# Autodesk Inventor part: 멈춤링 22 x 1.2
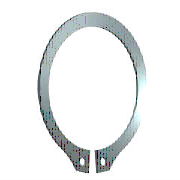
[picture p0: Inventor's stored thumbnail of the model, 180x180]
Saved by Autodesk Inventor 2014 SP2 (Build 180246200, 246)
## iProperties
IsCustomPart: 0
Created: 2015-11
Part Number: 멈춤링 22 x 1.2
Material: 스테인리스강
Description: 리테이닝 링(C형)
Document SubType Name: Modeling
Standard: KS B 1336
Designer: mdu
Standards Organization: KS
Language: ko-KR
Size Designation: 22 x 1.2
Categories: <MemberInstance><Categories><Category DisplayName="샤프트 부품" InternalName="7f7aeb1f-a693-4053-b835-cee3144e0d98" Mnemonic="SHFT"><Category DisplayName="써클립" Inter
Density: 8.08 g/cm^3
Appearance: 반광택
Mass: 1.87978 g
Surface Area: 5.91219 cm^2
Volume: 0.232646 cm^3
Author: mdu
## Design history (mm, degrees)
sketch "스케치1"
  geometry: L1 (-6, 0)-(6, 0) reference; L2 (0, 20.189)-(0, -80.536) reference; L3 (-48.09, 0)-(48.09, 0) reference; L4 (-0.5, -21.488)-(-0.5, -25.588); L5 (-0.5, -6.54)-(-0.5, -13.29); L6 (-2.795, 2.7)-(3.672, 2.7); L7 (0.5, -6.54)-(0.5, -13.29); L8 (0.5, -21.488)-(0.5, -25.588); C1 r 1 at (-2, -23.437); C2 r 1 at (2, -23.437); A1 r 10.5 centre (0, -11) between (0.5, -21.488) and (-0.5, -21.488); A2 r 13.025 centre (0, -10.325) between (5.149, -22.289) and (-5.149, -22.289); A3 r 14.597 centre (0, -11) between (-2.318, -25.411) and (-0.5, -25.588); A4 r 2 centre (-2, -23.437) between (-3.97, -23.781) and (-2.318, -25.411); A5 r 2 centre (-5.94, -24.126) between (-3.97, -23.781) and (-5.149, -22.289); A6 r 2 centre (5.94, -24.126) between (5.149, -22.289) and (3.97, -23.781); A7 r 2 centre (2, -23.437) between (2.318, -25.411) and (3.97, -23.781); A8 r 14.597 centre (0, -11) between (0.5, -25.588) and (2.318, -25.411)
  constraints: 16 point on circle, 12 end point, 10 centre point, 9 symmetric about line, 5 point on line, 4 tangent, 3 coincident, 2 horizontal, 1 perpendicular, 1 vertical, 5 other
  dimensions: "d0" = 21 diameter of A1 (= ND); "d1" = 4.1 distance of L4.end L4.start (= SRB2); "d6" = 0.5 distance between parallel lines of L2 L5 (= 0.25 x SD5); "d7" = 2.7 distance between parallel lines of L6 L3 (= SRB1); "d8" = 0.675 distance of A1.centre A2.centre (= 0.25 x SRB1); "d9" = 2 radius of A4 (= SD5); "d10" = 2 radius of A5 (= SD5); "d11" = 1.5 distance from line of L4 A4.centre (= 0.75 x SD5); "d12" = 2 diameter of C1 (= SD5); "d13" = 2 diameter of C2 (= SD5); "d14" = 11 distance from line of A1.centre L1 (= 0.5 x WD)
extrude "본체" new body sketch "스케치1" distance "d2" = 1.2 (= SD); taper "d3" = 0 deg
workaxis "Work Axis1"
workplane "Work Plane1"
body "Solid1"
other parameters: "WD" = 22 (= WDMIN) [user parameter; used in 1 equation term], "SD" = 1.2 [user parameter; used in 1 equation term], "SRB1" = 2.7 [user parameter; used in 2 equation terms], "ND" = 21 [user parameter; used in 1 equation term], "SRB2" = 4.1 [user parameter; used in 1 equation term], "SD5" = 2 [user parameter; used in 6 equation terms], "d15" = 0, "d16" = 0, "d17" = 0, "d41" = 0, "d42" = 0, "WDMIN" = 22 [user parameter; used in 1 equation term], "SD3" = 20.5 [user parameter], "WDMAX" = 24 [user parameter]
